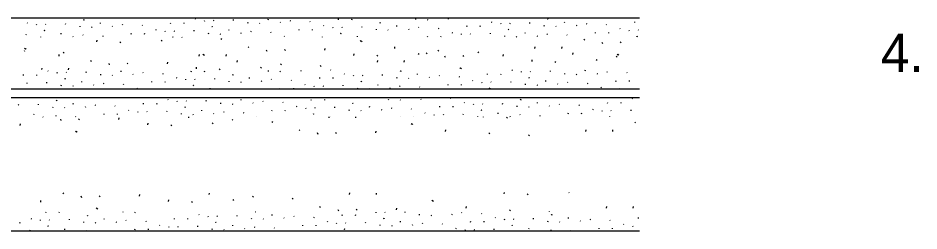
# Model space of a CAD drawing. Extents: x 99862 to 103151, y 100000 to 111076.
# Drawn here: x 100464.9 to 100840.9, y 110062.1 to 110151 of the extents above; entities that cross this region are included whole.
import ezdxf

# ---------------------------------------------------------------- set-up
doc = ezdxf.new("R2010")
doc.units = 0
for name, color, linetype in [('Level 11', 7, 'Continuous'), ('Level 18', 7, 'Continuous'), ('Level 20', 7, 'Continuous'), ('Level 24', 7, 'Continuous')]:
    doc.layers.add(name, color=color, linetype=linetype)

msp = doc.modelspace()

# ---------------------------------------------------------------- linework, layer by layer
at = {"layer": 'Level 11'}
for p, q in [((100389.11, 110151.04), (100724.21, 110151.04)), ((100165.98, 110117.79), (100724.21, 110117.79))]:
    msp.add_line(p, q, dxfattribs=at)
at = {"layer": 'Level 18'}
for p, q in [((100468.76, 110149.09), (100468.95, 110148.92)), ((100472.56, 110148.48), (100472.68, 110148.18)), ((100476.37, 110148.52), (100476.56, 110148.35)), ((100484.8, 110148.41), (100484.85, 110148.76)), ((100492.17, 110150.39), (100492.37, 110150.22)), ((100492.33, 110150.35), (100492.53, 110150.18)), ((100499.35, 110148.74), (100499.4, 110149.08)), ((100508.38, 110148.41), (100508.57, 110148.24)), ((100516.67, 110148.02), (100516.86, 110147.85)), ((100528.62, 110148.75), (100528.67, 110149.09)), ((100534.21, 110148.74), (100534.26, 110149.09)), ((100538.79, 110150.68), (100538.98, 110150.51)), ((100542.6, 110150.06), (100542.71, 110149.76)), ((100546.4, 110150.11), (100546.6, 110149.94)), ((100554.83, 110150), (100554.89, 110150.35)), ((100560.87, 110148.89), (100560.92, 110149.24)), ((100565.65, 110148.9), (100565.84, 110148.73)), ((100569.38, 110150.33), (100569.44, 110150.67)), ((100574.26, 110149.28), (100574.45, 110149.11)), ((100578.41, 110150), (100578.61, 110149.83)), ((100586.7, 110149.6), (100586.89, 110149.44)), ((100592.39, 110147.86), (100592.58, 110147.7)), ((100598.65, 110150.34), (100598.71, 110150.68)), ((100604.24, 110150.33), (100604.3, 110150.67)), ((100615.81, 110149.16), (100616, 110148.99)), ((100615.97, 110149.12), (100616.16, 110148.95)), ((100622.98, 110147.51), (100623.04, 110147.86)), ((100630.9, 110150.48), (100630.96, 110150.82)), ((100635.68, 110150.48), (100635.88, 110150.32)), ((100644.29, 110150.87), (100644.49, 110150.7)), ((100652.25, 110147.52), (100652.31, 110147.87)), ((100656.91, 110151.04), (100656.93, 110151.02)), ((100657.84, 110147.51), (100657.9, 110147.86)), ((100662.43, 110149.45), (100662.62, 110149.28)), ((100666.23, 110148.84), (100666.35, 110148.54)), ((100670.04, 110148.88), (100670.23, 110148.71)), ((100678.47, 110148.77), (100678.52, 110149.12)), ((100684.5, 110147.66), (100684.56, 110148.01)), ((100685.85, 110150.75), (100686.04, 110150.58)), ((100686, 110150.71), (100686.2, 110150.54)), ((100693.02, 110149.1), (100693.07, 110149.44)), ((100697.89, 110148.05), (100698.09, 110147.88)), ((100702.05, 110148.77), (100702.24, 110148.6)), ((100710.34, 110148.38), (100710.53, 110148.21)), ((100722.29, 110149.11), (100722.34, 110149.45)), ((100468.36, 110144.01), (100468.42, 110144.35)), ((100475.74, 110145.98), (100475.93, 110145.82)), ((100475.9, 110145.94), (100476.09, 110145.77)), ((100482.91, 110144.33), (100482.97, 110144.68)), ((100490.83, 110147.3), (100490.89, 110147.65)), ((100491.94, 110144), (100492.14, 110143.83)), ((100495.61, 110147.31), (100495.81, 110147.14)), ((100504.22, 110147.69), (100504.42, 110147.52)), ((100512.18, 110144.35), (100512.24, 110144.69)), ((100517.77, 110144.34), (100517.83, 110144.68)), ((100522.36, 110146.28), (100522.55, 110146.11)), ((100526.16, 110145.66), (100526.28, 110145.36)), ((100529.97, 110145.7), (100530.16, 110145.53)), ((100538.4, 110145.6), (100538.45, 110145.94)), ((100544.43, 110144.49), (100544.49, 110144.83)), ((100545.77, 110147.57), (100545.97, 110147.4)), ((100545.93, 110147.53), (100546.13, 110147.36)), ((100549.21, 110144.49), (100549.41, 110144.32)), ((100552.95, 110145.92), (100553, 110146.27)), ((100557.82, 110144.88), (100558.02, 110144.71)), ((100561.98, 110145.59), (100562.17, 110145.42)), ((100570.27, 110145.2), (100570.46, 110145.03)), ((100582.22, 110145.93), (100582.27, 110146.28)), ((100587.81, 110145.92), (100587.86, 110146.27)), ((100596.2, 110147.25), (100596.31, 110146.95)), ((100599.37, 110144.76), (100599.57, 110144.59)), ((100599.53, 110144.72), (100599.73, 110144.55)), ((100600, 110147.29), (100600.2, 110147.12)), ((100608.43, 110147.18), (100608.49, 110147.53)), ((100614.47, 110146.07), (100614.52, 110146.42)), ((100619.25, 110146.08), (100619.44, 110145.91)), ((100627.86, 110146.46), (100628.05, 110146.3)), ((100632.01, 110147.18), (100632.21, 110147.01)), ((100640.3, 110146.79), (100640.49, 110146.62)), ((100645.99, 110145.05), (100646.18, 110144.88)), ((100649.8, 110144.43), (100649.91, 110144.13)), ((100653.6, 110144.48), (100653.8, 110144.31)), ((100662.03, 110144.37), (100662.09, 110144.71)), ((100669.41, 110146.34), (100669.6, 110146.18)), ((100669.57, 110146.3), (100669.76, 110146.13)), ((100676.58, 110144.7), (100676.64, 110145.04)), ((100685.61, 110144.36), (100685.81, 110144.19)), ((100689.28, 110147.67), (100689.48, 110147.5)), ((100693.9, 110143.97), (100694.09, 110143.8)), ((100705.85, 110144.71), (100705.91, 110145.05)), ((100711.44, 110144.7), (100711.5, 110145.04)), ((100716.03, 110146.64), (100716.22, 110146.47)), ((100719.83, 110146.02), (100719.95, 110145.72)), ((100723.64, 110146.06), (100723.83, 110145.9)), ((100474.42, 110143.04), (100474.45, 110143.24)), ((100487.79, 110143.29), (100487.98, 110143.12)), ((100497.88, 110141.07), (100497.99, 110141.76)), ((100500.23, 110143.61), (100500.42, 110143.44)), ((100507.44, 110141.08), (100507.83, 110140.74)), ((100524.66, 110141.85), (100525.05, 110141.51)), ((100529.34, 110143.17), (100529.49, 110143.04)), ((100529.5, 110143.13), (100529.6, 110143.04)), ((100533.24, 110143.04), (100533.36, 110142.94)), ((100549.55, 110142.5), (100549.93, 110142.16)), ((100575.96, 110143.46), (100576.15, 110143.29)), ((100592.04, 110143.04), (100592.05, 110143.13)), ((100606.55, 110143.11), (100606.6, 110143.45)), ((100607.77, 110141.61), (100608.15, 110141.27)), ((100608.08, 110141.53), (100608.47, 110141.19)), ((100635.82, 110143.12), (100635.87, 110143.46)), ((100641.41, 110143.11), (100641.46, 110143.45)), ((100668.07, 110143.26), (100668.12, 110143.6)), ((100672.85, 110143.27), (100673.04, 110143.1)), ((100681.46, 110143.65), (100681.65, 110143.48)), ((100701, 110142.19), (100701.39, 110141.85)), ((100708.61, 110140.96), (100708.85, 110140.36)), ((100716.22, 110141.05), (100716.61, 110140.71)), ((100723.01, 110143.53), (100723.2, 110143.36)), ((100723.17, 110143.49), (100723.36, 110143.32)), ((100467.44, 110137.41), (100467.62, 110137.25)), ((100467.7, 110138.43), (100468.08, 110138.09)), ((100468.01, 110138.35), (100468.4, 110138.01)), ((100483.81, 110136.81), (100484.19, 110136.47)), ((100560.93, 110139.02), (100561.31, 110138.68)), ((100568.54, 110137.78), (100568.77, 110137.18)), ((100576.15, 110137.87), (100576.54, 110137.53)), ((100593.01, 110137.65), (100593.12, 110138.35)), ((100622.11, 110138.31), (100622.22, 110139)), ((100635.26, 110136.5), (100635.64, 110136.16)), ((100640.17, 110137.65), (100640.56, 110137.31)), ((100656.75, 110136.86), (100657.14, 110136.53)), ((100680.65, 110138.33), (100680.76, 110139.02)), ((100691.84, 110138.31), (100691.94, 110139)), ((100696.44, 110135.79), (100696.55, 110136.49)), ((100482.04, 110135.13), (100482.15, 110135.82)), ((100495.19, 110133.32), (100495.57, 110132.99)), ((100540.58, 110135.15), (100540.69, 110135.84)), ((100542.03, 110135.92), (100542.41, 110135.58)), ((100542.34, 110135.83), (100542.73, 110135.5)), ((100551.76, 110135.13), (100551.87, 110135.82)), ((100556.37, 110132.62), (100556.48, 110133.31)), ((100605.08, 110135.44), (100605.19, 110136.13)), ((100614.64, 110135.45), (100615.03, 110135.11)), ((100614.91, 110132.64), (100615.02, 110133.33)), ((100626.09, 110132.62), (100626.2, 110133.31)), ((100631.86, 110136.21), (100632.25, 110135.88)), ((100642.87, 110135.27), (100643.1, 110134.67)), ((100650.48, 110135.36), (100650.87, 110135.02)), ((100667.34, 110135.14), (100667.45, 110135.83)), ((100679.41, 110132.92), (100679.52, 110133.61)), ((100688.97, 110132.93), (100689.36, 110132.6)), ((100706.19, 110133.7), (100706.58, 110133.36)), ((100714.5, 110135.13), (100714.89, 110134.79)), ((100714.97, 110135.98), (100715.35, 110135.64)), ((100715.28, 110135.89), (100715.67, 110135.56)), ((100474.84, 110129.46), (100474.95, 110130.15)), ((100477.35, 110128.96), (100477.54, 110128.79)), ((100486.02, 110129.44), (100486.13, 110130.13)), ((100502.8, 110132.09), (100503.03, 110131.49)), ((100507.94, 110128.61), (100507.99, 110128.95)), ((100510.41, 110132.18), (100510.8, 110131.84)), ((100527.27, 110131.96), (100527.38, 110132.66)), ((100537.21, 110128.62), (100537.26, 110128.97)), ((100539.34, 110129.75), (100539.45, 110130.44)), ((100542.8, 110128.61), (100542.85, 110128.96)), ((100548.9, 110129.76), (100549.29, 110129.42)), ((100566.12, 110130.52), (100566.51, 110130.19)), ((100569.46, 110128.76), (100569.51, 110129.11)), ((100574.43, 110131.96), (100574.82, 110131.62)), ((100582.85, 110129.15), (100583.04, 110128.98)), ((100591.01, 110131.17), (100591.39, 110130.84)), ((100595.37, 110129.41), (100595.48, 110129.31)), ((100624.4, 110129.03), (100624.59, 110128.86)), ((100624.56, 110128.99), (100624.75, 110128.82)), ((100649.23, 110130.29), (100649.61, 110129.95)), ((100649.54, 110130.2), (100649.93, 110129.86)), ((100671.02, 110129.32), (100671.21, 110129.15)), ((100687.06, 110128.64), (100687.11, 110128.99)), ((100701.61, 110128.97), (100701.66, 110129.32)), ((100467.17, 110127.03), (100467.22, 110127.38)), ((100472.76, 110127.02), (100472.82, 110127.37)), ((100481.15, 110128.35), (100481.27, 110128.05)), ((100484.33, 110125.86), (100484.52, 110125.69)), ((100484.49, 110125.81), (100484.68, 110125.64)), ((100484.96, 110128.39), (100485.15, 110128.22)), ((100493.39, 110128.28), (100493.44, 110128.63)), ((100499.42, 110127.17), (100499.47, 110127.52)), ((100504.2, 110127.18), (100504.39, 110127.01)), ((100512.81, 110127.56), (100513, 110127.39)), ((100516.97, 110128.28), (100517.16, 110128.11)), ((100525.26, 110127.89), (100525.45, 110127.72)), ((100530.95, 110126.15), (100531.14, 110125.98)), ((100534.75, 110125.53), (100534.87, 110125.23)), ((100538.56, 110125.57), (100538.75, 110125.41)), ((100546.99, 110125.47), (100547.04, 110125.81)), ((100554.36, 110127.44), (100554.56, 110127.27)), ((100554.52, 110127.4), (100554.71, 110127.23)), ((100561.54, 110125.79), (100561.59, 110126.14)), ((100570.57, 110125.46), (100570.76, 110125.29)), ((100574.24, 110128.77), (100574.43, 110128.6)), ((100590.81, 110125.8), (100590.86, 110126.15)), ((100596.4, 110125.79), (100596.45, 110126.14)), ((100600.98, 110127.73), (100601.17, 110127.57)), ((100604.79, 110127.12), (100604.9, 110126.82)), ((100608.59, 110127.16), (100608.78, 110126.99)), ((100617.02, 110127.05), (100617.08, 110127.4)), ((100623.06, 110125.95), (100623.11, 110126.29)), ((100627.84, 110125.95), (100628.03, 110125.78)), ((100631.57, 110127.38), (100631.63, 110127.73)), ((100636.45, 110126.33), (100636.64, 110126.17)), ((100640.6, 110127.05), (100640.79, 110126.88)), ((100648.89, 110126.66), (100649.08, 110126.49)), ((100660.84, 110127.39), (100660.9, 110127.74)), ((100666.43, 110127.38), (100666.49, 110127.73)), ((100674.82, 110128.71), (100674.94, 110128.41)), ((100678, 110126.22), (100678.19, 110126.05)), ((100678.16, 110126.17), (100678.35, 110126.01)), ((100678.63, 110128.75), (100678.82, 110128.58)), ((100693.09, 110127.53), (100693.15, 110127.88)), ((100697.87, 110127.54), (100698.07, 110127.37)), ((100706.48, 110127.92), (100706.68, 110127.75)), ((100710.64, 110128.64), (100710.83, 110128.47)), ((100718.93, 110128.25), (100719.12, 110128.08)), ((100467.89, 110121.45), (100467.94, 110121.41)), ((100468.05, 110121.41), (100468.05, 110121.41)), ((100468.52, 110123.99), (100468.71, 110123.82)), ((100476.95, 110123.88), (100477.01, 110124.22)), ((100482.99, 110122.77), (100483.04, 110123.12)), ((100487.77, 110122.78), (100487.96, 110122.61)), ((100491.5, 110124.21), (100491.55, 110124.55)), ((100496.38, 110123.16), (100496.57, 110122.99)), ((100500.53, 110123.87), (100500.72, 110123.7)), ((100508.82, 110123.48), (100509.01, 110123.31)), ((100514.51, 110121.74), (100514.7, 110121.57)), ((100520.77, 110124.22), (100520.83, 110124.56)), ((100526.36, 110124.21), (100526.42, 110124.55)), ((100530.61, 110121.41), (100530.61, 110121.41)), ((100537.93, 110123.04), (100538.12, 110122.87)), ((100538.09, 110123), (100538.28, 110122.83)), ((100545.1, 110121.41), (100545.15, 110121.74)), ((100553.02, 110124.36), (100553.07, 110124.7)), ((100557.8, 110124.36), (100557.99, 110124.19)), ((100566.41, 110124.75), (100566.61, 110124.58)), ((100574.37, 110121.41), (100574.43, 110121.75)), ((100578.86, 110125.07), (100579.05, 110124.9)), ((100579.97, 110121.41), (100580.02, 110121.74)), ((100584.55, 110123.33), (100584.74, 110123.16)), ((100588.35, 110122.71), (100588.47, 110122.41)), ((100592.16, 110122.76), (100592.35, 110122.59)), ((100600.59, 110122.65), (100600.64, 110123)), ((100606.62, 110121.54), (100606.68, 110121.89)), ((100607.96, 110124.63), (100608.16, 110124.46)), ((100608.12, 110124.59), (100608.31, 110124.42)), ((100611.4, 110121.55), (100611.56, 110121.41)), ((100615.14, 110122.98), (100615.19, 110123.32)), ((100620.01, 110121.93), (100620.21, 110121.76)), ((100624.17, 110122.65), (100624.36, 110122.48)), ((100632.46, 110122.26), (100632.65, 110122.09)), ((100644.41, 110122.99), (100644.46, 110123.33)), ((100650, 110122.98), (100650.05, 110123.32)), ((100654.58, 110124.92), (100654.77, 110124.75)), ((100658.39, 110124.3), (100658.5, 110124)), ((100661.56, 110121.81), (100661.76, 110121.64)), ((100661.72, 110121.77), (100661.91, 110121.6)), ((100662.19, 110124.35), (100662.38, 110124.18)), ((100670.62, 110124.24), (100670.68, 110124.58)), ((100676.66, 110123.13), (100676.71, 110123.48)), ((100681.44, 110123.14), (100681.63, 110122.97)), ((100685.17, 110124.57), (100685.23, 110124.91)), ((100690.05, 110123.52), (100690.24, 110123.35)), ((100694.2, 110124.23), (100694.4, 110124.07)), ((100702.49, 110123.84), (100702.68, 110123.67)), ((100708.18, 110122.1), (100708.37, 110121.93)), ((100711.99, 110121.49), (100712.02, 110121.41)), ((100714.44, 110124.58), (100714.5, 110124.92)), ((100715.79, 110121.53), (100715.93, 110121.41)), ((100720.03, 110124.57), (100720.09, 110124.91)), ((100601.38, 110117.79), (100601.42, 110117.69)), ((100637.27, 110117.79), (100637.31, 110117.75)), ((100465.03, 110114.86), (100465.23, 110114.69)), ((100473.46, 110114.75), (100473.52, 110115.09)), ((100479.5, 110113.64), (100479.55, 110113.98)), ((100480.84, 110116.72), (100481.03, 110116.56)), ((100481, 110116.68), (100481.19, 110116.51)), ((100488.01, 110115.07), (100488.07, 110115.42)), ((100492.89, 110114.03), (100493.08, 110113.86)), ((100497.04, 110114.74), (100497.24, 110114.57)), ((100505.33, 110114.35), (100505.52, 110114.18)), ((100517.28, 110115.09), (100517.34, 110115.43)), ((100522.87, 110115.08), (100522.93, 110115.42)), ((100527.46, 110117.02), (100527.65, 110116.85)), ((100531.26, 110116.4), (100531.38, 110116.1)), ((100534.44, 110113.91), (100534.63, 110113.74)), ((100535.07, 110116.44), (100535.26, 110116.28)), ((100543.5, 110116.34), (100543.55, 110116.68)), ((100549.53, 110115.23), (100549.59, 110115.57)), ((100554.31, 110115.23), (100554.51, 110115.06)), ((100558.05, 110116.66), (100558.1, 110117.01)), ((100562.92, 110115.62), (100563.12, 110115.45)), ((100567.08, 110116.33), (100567.27, 110116.16)), ((100575.37, 110115.94), (100575.56, 110115.77)), ((100581.06, 110114.2), (100581.25, 110114.03)), ((100587.32, 110116.67), (100587.37, 110117.02)), ((100592.91, 110116.66), (100592.96, 110117.01)), ((100604.48, 110115.5), (100604.67, 110115.33)), ((100604.63, 110115.46), (100604.83, 110115.29)), ((100611.65, 110113.85), (100611.7, 110114.19)), ((100619.57, 110116.82), (100619.62, 110117.16)), ((100624.35, 110116.82), (100624.54, 110116.65)), ((100632.96, 110117.2), (100633.15, 110117.04)), ((100640.92, 110113.86), (100640.97, 110114.2)), ((100645.4, 110117.53), (100645.6, 110117.36)), ((100646.51, 110113.85), (100646.56, 110114.19)), ((100651.09, 110115.79), (100651.29, 110115.62)), ((100654.9, 110115.17), (100655.02, 110114.87)), ((100658.7, 110115.22), (100658.9, 110115.05)), ((100667.13, 110115.11), (100667.19, 110115.45)), ((100673.17, 110114), (100673.22, 110114.34)), ((100674.51, 110117.09), (100674.7, 110116.92)), ((100674.67, 110117.04), (100674.86, 110116.87)), ((100677.95, 110114.01), (100678.14, 110113.84)), ((100681.68, 110115.44), (100681.74, 110115.78)), ((100686.56, 110114.39), (100686.75, 110114.22)), ((100690.71, 110115.1), (100690.91, 110114.93)), ((100699, 110114.71), (100699.2, 110114.54)), ((100710.95, 110115.45), (100711.01, 110115.79)), ((100716.55, 110115.44), (100716.6, 110115.78)), ((100721.13, 110117.38), (100721.32, 110117.21)), ((100471.58, 110110.67), (100471.63, 110111.02)), ((100480.61, 110110.34), (100480.8, 110110.17)), ((100484.28, 110113.64), (100484.47, 110113.48)), ((100500.85, 110110.68), (100500.9, 110111.03)), ((100506.44, 110110.67), (100506.49, 110111.02)), ((100511.02, 110112.61), (100511.21, 110112.44)), ((100514.83, 110112), (100514.94, 110111.7)), ((100518.63, 110112.04), (100518.83, 110111.87)), ((100527.06, 110111.93), (100527.12, 110112.28)), ((100533.1, 110110.82), (100533.15, 110111.17)), ((100534.6, 110113.87), (100534.79, 110113.7)), ((100537.88, 110110.83), (100538.07, 110110.66)), ((100541.61, 110112.26), (100541.67, 110112.6)), ((100546.49, 110111.21), (100546.68, 110111.04)), ((100550.64, 110111.93), (100550.84, 110111.76)), ((100558.93, 110111.54), (100559.12, 110111.37)), ((100570.88, 110112.27), (100570.94, 110112.61)), ((100576.47, 110112.26), (100576.53, 110112.61)), ((100584.86, 110113.58), (100584.98, 110113.28)), ((100588.04, 110111.09), (100588.23, 110110.92)), ((100588.2, 110111.05), (100588.39, 110110.88)), ((100588.67, 110113.63), (100588.86, 110113.46)), ((100597.1, 110113.52), (100597.15, 110113.87)), ((100603.13, 110112.41), (100603.19, 110112.76)), ((100607.91, 110112.42), (100608.11, 110112.25)), ((100616.52, 110112.8), (100616.72, 110112.63)), ((100620.68, 110113.52), (100620.87, 110113.35)), ((100628.97, 110113.13), (100629.16, 110112.96)), ((100634.66, 110111.38), (100634.85, 110111.22)), ((100638.46, 110110.77), (100638.58, 110110.47)), ((100642.27, 110110.81), (100642.46, 110110.64)), ((100650.7, 110110.7), (100650.75, 110111.05)), ((100658.08, 110112.68), (100658.27, 110112.51)), ((100658.23, 110112.64), (100658.43, 110112.47)), ((100665.25, 110111.03), (100665.3, 110111.38)), ((100674.28, 110110.7), (100674.47, 110110.53)), ((100682.57, 110110.31), (100682.76, 110110.14)), ((100694.52, 110111.04), (100694.57, 110111.39)), ((100700.11, 110111.03), (100700.16, 110111.38)), ((100704.69, 110112.97), (100704.89, 110112.8)), ((100708.5, 110112.36), (100708.62, 110112.06)), ((100712.3, 110112.4), (100712.5, 110112.23)), ((100720.73, 110112.29), (100720.79, 110112.64)), ((100465.82, 110106.13), (100465.93, 110106.82)), ((100475.24, 110109.79), (100475.37, 110109.67)), ((100482.59, 110108.78), (100482.83, 110108.18)), ((100488.9, 110109.95), (100489.08, 110109.79)), ((100490.2, 110108.87), (100490.59, 110108.53)), ((100507.06, 110108.65), (100507.17, 110109.34)), ((100519.13, 110106.43), (100519.24, 110107.12)), ((100528.7, 110106.44), (100529.08, 110106.11)), ((100536.16, 110109.3), (100536.24, 110109.79)), ((100545.92, 110107.21), (100546.3, 110106.87)), ((100554.23, 110108.64), (100554.61, 110108.3)), ((100564.62, 110109.8), (100564.63, 110109.79)), ((100570.8, 110107.86), (100571.19, 110107.52)), ((100594.7, 110109.32), (100594.78, 110109.79)), ((100595.27, 110109.79), (100595.27, 110109.79)), ((100605.89, 110109.31), (100605.96, 110109.79)), ((100624.54, 110109.79), (100624.54, 110109.8)), ((100629.02, 110106.97), (100629.4, 110106.63)), ((100629.33, 110106.89), (100629.72, 110106.55)), ((100630.13, 110109.79), (100630.13, 110109.79)), ((100656.76, 110109.79), (100656.79, 110109.94)), ((100659.2, 110109.61), (100659.23, 110109.79)), ((100668.77, 110109.62), (100669.15, 110109.28)), ((100670.13, 110109.98), (100670.32, 110109.82)), ((100711.68, 110109.87), (100711.77, 110109.79)), ((100711.83, 110109.82), (100711.88, 110109.79)), ((100722.25, 110107.56), (100722.64, 110107.22)), ((100488.95, 110103.8), (100489.33, 110103.46)), ((100489.26, 110103.71), (100489.65, 110103.38)), ((100582.18, 110104.38), (100582.57, 110104.04)), ((100589.79, 110103.15), (100590.03, 110102.55)), ((100597.4, 110103.24), (100597.79, 110102.9)), ((100614.26, 110103.02), (100614.37, 110103.71)), ((100643.36, 110103.67), (100643.47, 110104.36)), ((100661.43, 110103.01), (100661.81, 110102.67)), ((100701.9, 110103.69), (100702.01, 110104.38)), ((100713.09, 110103.67), (100713.2, 110104.37)), ((100678, 110102.23), (100678.39, 110101.89)), ((100483.57, 110077.96), (100483.96, 110077.62)), ((100491.18, 110076.72), (100491.42, 110076.12)), ((100498.79, 110076.81), (100499.18, 110076.47)), ((100515.65, 110076.6), (100515.76, 110077.29)), ((100544.75, 110077.25), (100544.86, 110077.94)), ((100562.81, 110076.59), (100563.2, 110076.25)), ((100603.29, 110077.27), (100603.4, 110077.96)), ((100614.48, 110077.25), (100614.58, 110077.94)), ((100667.79, 110077.55), (100667.88, 110078.14)), ((100677.36, 110077.57), (100677.74, 110077.23)), ((100694.79, 110078.14), (100694.96, 110077.99)), ((100474.41, 110074.08), (100474.51, 110074.77)), ((100527.72, 110074.38), (100527.83, 110075.07)), ((100537.28, 110074.39), (100537.67, 110074.05)), ((100554.51, 110075.16), (100554.89, 110074.82)), ((100579.39, 110075.81), (100579.78, 110075.47)), ((100637.61, 110074.92), (100637.99, 110074.58)), ((100637.92, 110074.84), (100638.31, 110074.5)), ((100476.57, 110069.82), (100476.61, 110070.11)), ((100482.16, 110069.81), (100482.21, 110070.11)), ((100497.54, 110071.74), (100497.92, 110071.4)), ((100497.85, 110071.66), (100498.24, 110071.32)), ((100508.82, 110069.96), (100508.84, 110070.12)), ((100513.6, 110069.97), (100513.79, 110069.8)), ((100540.34, 110068.93), (100540.53, 110068.77)), ((100563.88, 110070.12), (100563.95, 110070.06)), ((100563.99, 110070.12), (100564.11, 110070.02)), ((100570.93, 110068.58), (100570.99, 110068.93)), ((100590.77, 110072.33), (100591.16, 110071.99)), ((100598.38, 110071.09), (100598.62, 110070.49)), ((100600.2, 110068.59), (100600.26, 110068.94)), ((100605.79, 110068.58), (100605.85, 110068.93)), ((100605.99, 110071.18), (100606.38, 110070.84)), ((100614.18, 110069.91), (100614.3, 110069.61)), ((100617.99, 110069.95), (100618.18, 110069.78)), ((100622.85, 110070.97), (100622.96, 110071.66)), ((100626.42, 110069.84), (100626.46, 110070.13)), ((100632.45, 110068.73), (100632.51, 110069.08)), ((100645.84, 110069.12), (100646.04, 110068.95)), ((100650, 110069.84), (100650.19, 110069.67)), ((100651.95, 110071.62), (100652.06, 110072.31)), ((100658.29, 110069.45), (100658.48, 110069.28)), ((100670.01, 110070.96), (100670.4, 110070.62)), ((100686.59, 110070.17), (100686.63, 110070.14)), ((100687.39, 110069), (100687.59, 110068.83)), ((100687.55, 110068.96), (100687.75, 110068.79)), ((100710.49, 110071.64), (100710.6, 110072.33)), ((100721.68, 110071.62), (100721.79, 110072.31)), ((100465.72, 110065.41), (100465.78, 110065.75)), ((100470.31, 110067.35), (100470.5, 110067.18)), ((100474.11, 110066.73), (100474.23, 110066.43)), ((100477.92, 110066.77), (100478.11, 110066.61)), ((100486.35, 110066.67), (100486.4, 110067.01)), ((100492.38, 110065.56), (100492.43, 110065.9)), ((100493.72, 110068.64), (100493.92, 110068.47)), ((100493.88, 110068.6), (100494.07, 110068.43)), ((100497.16, 110065.56), (100497.36, 110065.39)), ((100500.9, 110066.99), (100500.95, 110067.34)), ((100505.77, 110065.95), (100505.97, 110065.78)), ((100509.93, 110066.66), (100510.12, 110066.49)), ((100518.22, 110066.27), (100518.41, 110066.1)), ((100530.17, 110067), (100530.22, 110067.35)), ((100535.76, 110066.99), (100535.81, 110067.34)), ((100544.15, 110068.32), (100544.26, 110068.02)), ((100547.32, 110065.83), (100547.52, 110065.66)), ((100547.48, 110065.79), (100547.67, 110065.62)), ((100547.95, 110068.36), (100548.14, 110068.19)), ((100556.38, 110068.25), (100556.44, 110068.6)), ((100562.42, 110067.15), (100562.47, 110067.49)), ((100567.2, 110067.15), (100567.39, 110066.98)), ((100575.81, 110067.53), (100576, 110067.37)), ((100579.96, 110068.25), (100580.15, 110068.08)), ((100588.25, 110067.86), (100588.44, 110067.69)), ((100593.94, 110066.12), (100594.13, 110065.95)), ((100597.75, 110065.5), (100597.86, 110065.2)), ((100601.55, 110065.55), (100601.74, 110065.38)), ((100609.98, 110065.44), (100610.04, 110065.78)), ((100617.36, 110067.42), (100617.55, 110067.25)), ((100617.52, 110067.37), (100617.71, 110067.2)), ((100624.53, 110065.77), (100624.59, 110066.11)), ((100633.56, 110065.43), (100633.76, 110065.26)), ((100637.23, 110068.74), (100637.43, 110068.57)), ((100641.85, 110065.04), (100642.04, 110064.87)), ((100653.8, 110065.78), (100653.86, 110066.12)), ((100659.39, 110065.77), (100659.45, 110066.11)), ((100663.98, 110067.71), (100664.17, 110067.54)), ((100667.78, 110067.09), (100667.9, 110066.79)), ((100671.59, 110067.13), (100671.78, 110066.97)), ((100680.02, 110067.03), (100680.07, 110067.37)), ((100686.05, 110065.92), (100686.11, 110066.26)), ((100690.83, 110065.92), (100691.03, 110065.75)), ((100694.57, 110067.35), (100694.62, 110067.7)), ((100699.44, 110066.31), (100699.64, 110066.14)), ((100703.6, 110067.02), (100703.79, 110066.85)), ((100711.89, 110066.63), (100712.08, 110066.46)), ((100723.84, 110067.36), (100723.89, 110067.71)), ((100469.91, 110062.26), (100469.97, 110062.61)), ((100477.29, 110064.24), (100477.48, 110064.07)), ((100477.45, 110064.2), (100477.64, 110064.03)), ((100484.46, 110062.59), (100484.51, 110062.94)), ((100493.49, 110062.26), (100493.66, 110062.11)), ((100513.73, 110062.6), (100513.79, 110062.95)), ((100519.32, 110062.59), (100519.38, 110062.94)), ((100523.91, 110064.53), (100524.1, 110064.36)), ((100527.71, 110063.91), (100527.83, 110063.61)), ((100531.52, 110063.96), (100531.71, 110063.79)), ((100539.95, 110063.85), (100540, 110064.2)), ((100545.98, 110062.74), (100546.04, 110063.09)), ((100550.76, 110062.75), (100550.96, 110062.58)), ((100554.5, 110064.18), (100554.55, 110064.52)), ((100559.37, 110063.13), (100559.57, 110062.96)), ((100563.53, 110063.85), (100563.72, 110063.68)), ((100571.82, 110063.46), (100572.01, 110063.29)), ((100583.77, 110064.19), (100583.82, 110064.53)), ((100589.36, 110064.18), (100589.41, 110064.52)), ((100600.92, 110063.01), (100601.12, 110062.84)), ((100601.08, 110062.97), (100601.27, 110062.8)), ((100616.02, 110064.33), (100616.07, 110064.68)), ((100620.8, 110064.34), (100620.99, 110064.17)), ((100629.41, 110064.72), (100629.6, 110064.55)), ((100647.54, 110063.3), (100647.73, 110063.13)), ((100651.35, 110062.69), (100651.46, 110062.39)), ((100655.15, 110062.73), (100655.35, 110062.56)), ((100663.58, 110062.62), (100663.64, 110062.97)), ((100670.96, 110064.6), (100671.15, 110064.43)), ((100671.12, 110064.56), (100671.31, 110064.39)), ((100678.13, 110062.95), (100678.19, 110063.3)), ((100687.16, 110062.62), (100687.36, 110062.45)), ((100695.45, 110062.23), (100695.55, 110062.14)), ((100707.4, 110062.96), (100707.46, 110063.31)), ((100712.99, 110062.95), (100713.05, 110063.3)), ((100717.58, 110064.89), (100717.77, 110064.72)), ((100721.38, 110064.27), (100721.5, 110063.97))]:
    msp.add_line(p, q, dxfattribs=at)
at = {"layer": 'Level 24'}
for p, q in [((100174.51, 110121.41), (100724.21, 110121.41)), ((100168.04, 110062.07), (100724.21, 110062.14))]:
    msp.add_line(p, q, dxfattribs=at)

# ---------------------------------------------------------------- texts
at = {"layer": 'Level 20'}
msp.add_text('4.', height=16, dxfattribs=at).set_placement((100824.99, 110128.55))

doc.saveas('drawing.dxf')
